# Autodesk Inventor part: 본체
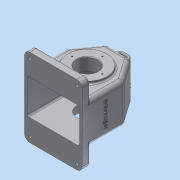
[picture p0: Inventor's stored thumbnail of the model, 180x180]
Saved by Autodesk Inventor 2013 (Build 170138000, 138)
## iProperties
Created: 2016-12
Part Number: 본체
Material: 알루미늄 6061
Document SubType Name: Modeling
Designer: dgall
Density: 2.71 g/cm^3
Mass: 1067.05 g
Surface Area: 1138.25 cm^2
Volume: 393.746 cm^3
Author: dgall
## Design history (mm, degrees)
sketch "스케치1"
  geometry: L1 (-23.491, 85)-(-55, 40); L2 (-55, 40)-(-55, -40); L3 (-55, -40)-(55, -40); L4 (55, -40)-(55, 40); L5 (55, 40)-(23.491, 85); L6 (23.491, 85)-(-23.491, 85); L7 (-20.888, 80)-(-50, 38.424); L8 (-50, 38.424)-(-50, -40); L9 (50, -40)-(50, 38.424); L10 (50, 38.424)-(20.888, 80); L11 (20.888, 80)-(-20.888, 80); 4 further points
  constraints: 22 end point, 3 midpoint, 3 point on line, 2 vertical, 2 vertical alignment, 1 equal length, 1 horizontal, 1 horizontal alignment, 1 perpendicular, 3 other
  dimensions: "d0" = 80 distance of L3.end L4.end; "d2" = 35 deg angle of L2 L1; "d4" = 35 deg angle of L4 L5; "d6" = 125 distance between parallel lines of L3 L6; "d7" = 110 distance of L2.end L3.end; "d8" = 5 distance between parallel lines of L5 L10; "d9" = 5 distance between parallel lines of L1 L7
extrude "돌출1" new body sketch "스케치1" stored distance "d10" = 77; taper "d11" = 0 deg
extrude "돌출2" cut sketch "스케치1" stored distance "d12" = 67; taper "d13" = 0 deg
sketch "스케치2"
  geometry: L1 (85, -38.5)-(-40, -38.5) reference; L2 (-40, -38.5)-(-40, -33.5) reference; L3 (-40, -33.5)-(80, -33.5) reference; L4 (80, -33.5)-(80, 33.5) reference; L5 (80, 33.5)-(-40, 33.5) reference; L6 (-40, 33.5)-(-40, 38.5) reference; L7 (-40, 38.5)-(85, 38.5) reference; L8 (85, 38.5)-(85, -38.5) reference; L9 (25, 38.5)-(25, -38.5); L10 (-40, -33.5)-(-40, 33.5) reference; L11 (66, 33.5)-(52, 19.5); L12 (52, 19.5)-(25, 19.5); L13 (25, 38.5)-(25, 43.5); L14 (25, 43.5)-(62.5, 43.5); L15 (62.5, 43.5)-(62.5, 38.5); L16 (66, 33.5)-(66, 38.5); L17 (62.5, 38.5)-(66, 38.5); 1 further point
  constraints: 16 end point, 6 perpendicular, 6 point on line, 1 collinear
  dimensions: "d14" = 65 distance between parallel lines of L10 L9; "d16" = 24 distance between parallel lines of L12 L14; "d17" = 45 deg angle of L12 L11; "d18" = 5 distance from line of L14.end L7; "d19" = 27 distance from line of L9 L11.end; "d20" = 37.5 distance between parallel lines of L9 L15
revolve "회전1" sketch "스케치2" stored, may be unused: angle "d21" = 90 deg
node "작업 평면1"
sketch "스케치3" dims "d25" = 52
  geometry: C1 r 37.5 at (0, 25) reference; C2 r 20 at (0, 25); C3 r 31 at (0, 25); 3 further points
  constraints: 3 coincident, 2 centre point, 2 vertical alignment, 2 other
  dimensions: "d23" = 62 diameter of C3; "d26" = 40 diameter of C2
extrude "돌출3" join sketch "스케치3" stored distance "d27" = 67; taper "d28" = 0 deg
extrude "돌출4" cut sketch "스케치3" stored distance "d29" = 67; taper "d30" = 0 deg
hole "구멍1" sketch "스케치3" diameter "d31" = 2.459; stored, may be unused: countersink angle "d35" = 90 deg, drill point angle "d37" = 118 deg; dims "d32" = 6, "d33" = 4, "d34" = 2, "d36" = 8
sketch "스케치4" dims "d41" = 58
  geometry: C1 r 20 at (0, 0) reference; C2 r 37.5 at (0, 0) reference; 3 further points
  constraints: 2 vertical alignment, 1 coincident, 2 other
hole "구멍2" sketch "스케치4" at (0, 29) diameter "d43" = 2.459; stored, may be unused: countersink angle "d47" = 90 deg, drill point angle "d49" = 118 deg; dims "d44" = 6, "d45" = 4, "d46" = 2, "d48" = 8
sketch "스케치5"
  geometry: L1 (110, -77)-(110, 0) reference; L2 (0, 0)-(110, 0) reference; L3 (0, -77)-(0, 0) reference; L4 (110, -77)-(0, -77) reference; L5 (0, 36.5)-(110, 36.5); L6 (110, 36.5)-(110, -113.5); L7 (110, -113.5)-(0, -113.5); L8 (0, -113.5)-(0, 36.5); 3 further points
  constraints: 8 end point, 2 midpoint, 2 parallel, 1 horizontal, 1 horizontal alignment, 1 perpendicular, 1 vertical alignment
  dimensions: "d53" = 110 distance of L5.start L5.end; "d55" = 150 distance of L5.end L6.end
extrude "돌출5" join sketch "스케치5" distance "d56" = 15; taper "d57" = 0 deg
node "작업 평면2"
sketch "스케치6"
  geometry: L1 (-55, 40)-(-23.491, 85) reference; L2 (-23.491, 85)-(23.491, 85) reference; L3 (23.491, 85)-(55, 40) reference; L4 (55, 40)-(55, -40) reference; L5 (55, -40)-(50, -40) reference; L6 (50, -40)-(50, 38.424) reference; L7 (50, 38.424)-(20.888, 80) reference; L8 (20.888, 80)-(-20.888, 80) reference; L9 (-20.888, 80)-(-50, 38.424) reference; L10 (-50, 38.424)-(-50, -40) reference; L11 (-50, -40)-(-55, -40) reference; L12 (-55, -40)-(-55, 40) reference; L13 (-12.5, 85)-(-12.5, 100); L14 (-12.5, 100)-(12.5, 100); L15 (12.5, 100)-(12.5, 85); L16 (7.5, 85)-(7.5, 95); L17 (7.5, 95)-(-7.5, 95); L18 (-7.5, 95)-(-7.5, 85); L19 (50, -40)-(-50, -40) reference; 3 further points
  constraints: 12 end point, 4 point on line, 3 perpendicular, 2 midpoint, 2 vertical alignment, 1 parallel, 2 other
  dimensions: "d59" = 25 distance of L13.end L14.end; "d61" = 15 distance of L16.end L17.end; "d62" = 140 distance between parallel lines of L14 L19
extrude "돌출6" join sketch "스케치6" distance "d63" = 8; taper "d64" = 0 deg
node "작업 평면3"
sketch "스케치7"
  geometry: L1 (-36.5, -80)-(-36.5, -65) reference; L2 (113.5, -80)-(-36.5, -80) reference; L3 (0, -65)-(0, 0) reference; 2 further points
  constraints: 1 other
  dimensions: "d67" = 45 distance from line of L2 point (38.5, -35); "d68" = 38.5 distance from line of point (38.5, -35) L3
feature "엠보싱1" sketch "스케치7" dims "d69" = 0.5, "d70" = 0
fillet "모깎기1" dims "d71" = 10, "d72" = 3
fillet "모깎기2" dims "d73" = 8, "d74" = 3
fillet "모깎기3" dims "d75" = 10
sketch "스케치8"
  geometry: L1 (10, -36.5)-(100, -36.5) reference; L2 (110, -26.5)-(110, 8) reference; L3 (8, 0)-(102, 0) reference; L4 (0, 8)-(0, -26.5) reference; A1 r 10 centre (10, 103.5) between (10, 113.5) and (0, 103.5) reference; A2 r 10 centre (100, 103.5) between (110, 103.5) and (100, 113.5) reference; A3 r 10 centre (10, -26.5) between (0, -26.5) and (10, -36.5) reference; A4 r 10 centre (100, -26.5) between (100, -36.5) and (110, -26.5) reference; A5 r 8 centre (102, 8) between (102, 0) and (110, 8) reference; A6 r 8 centre (8, 8) between (0, 8) and (8, 0) reference; 1 further point
hole "구멍3" sketch "스케치8" at (100, 103.5), (10, 103.5), (10, -26.5), (100, -26.5) diameter "d76" = 5; stored, may be unused: countersink angle "d80" = 90 deg, drill point angle "d82" = 118 deg; dims "d77" = 6, "d78" = 12, "d79" = 5, "d81" = 8
fillet "모깎기4" dims "d83" = 8, "d84" = 3
fillet "모깎기5" dims "d85" = 1
fillet "모깎기6" dims "d86" = 1
fillet "모깎기7" dims "d87" = 1
fillet "모깎기8" dims "d88" = 3
chamfer "모따기1" distance "d89" = 1; stored, may be unused: second distance "d90" = 2, angle "d91" = 45 deg
node "솔리드1"
pattern_circular "원형 패턴1" dims angle "d39" = 360 deg
pattern_circular "원형 패턴2" dims angle "d51" = 360 deg
mirror "대칭1"
node "투영된 루프1"
node "절단 모서리 투영1"
node "절단 모서리 투영2"
other parameters: "d58" = 18
